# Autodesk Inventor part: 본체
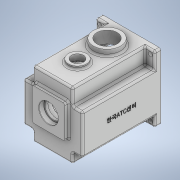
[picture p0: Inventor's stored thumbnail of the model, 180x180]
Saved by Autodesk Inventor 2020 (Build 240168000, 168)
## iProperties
Created: 2022-01
Part Number: 본체
Material: 일반
Document SubType Name: Modeling
Designer: user
Density: 1 g/cm^3
Appearance: 기본값
Mass: 520.049 g
Surface Area: 1170.68 cm^2
Volume: 520.049 cm^3
Author: user
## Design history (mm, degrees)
sketch "스케치1"
  geometry: L1 (-49, -55)-(49, -55); L2 (49, -55)-(49, 55); L3 (49, 55)-(-49, 55); L4 (-49, 55)-(-49, -55); L5 (-49, -55)-(49, 55); L6 (49, -55)-(-49, 55); 1 further point
  constraints: 12 end point, 2 midpoint, 2 parallel, 1 horizontal, 1 perpendicular
  dimensions: "d0" = 98 distance of L3.end L2.end; "d1" = 110 distance of L2.end L1.end
extrude "돌출1" new body sketch "스케치1" stored distance "d2" = 130; taper "d3" = 0 deg
sketch "스케치2"
  geometry: L1 (49, 55)-(-49, 55) reference; L2 (49, -55)-(49, 55) reference; L3 (33, 55)-(49, 55); L4 (49, 55)-(49, 28); L5 (49, 28)-(33, 28); L6 (33, 28)-(33, 55); L7 (33, -38)-(49, -38); L8 (49, -38)-(49, -55); L9 (49, -55)-(33, -55); L10 (33, -55)-(33, -38); L11 (-49, 55)-(-49, -55) reference; L12 (-49, 55)-(-33, 55); L13 (-33, 55)-(-33, 28); L14 (-33, 28)-(-49, 28); L15 (-49, 28)-(-49, 55); L16 (-49, -55)-(49, -55) reference; L17 (-49, -38)-(-33, -38); L18 (-33, -38)-(-33, -55); L19 (-33, -55)-(-49, -55); L20 (-49, -55)-(-49, -38); 5 further points
  constraints: 32 end point, 8 parallel, 8 point on line, 4 horizontal, 4 perpendicular
  dimensions: "d4" = 27 distance of L5.end L3.start; "d5" = 17 distance of L9.end L7.start; "d6" = 27 distance of L12.end L13.end; "d7" = 17 distance of L17.end L18.end; "d8" = 16 distance of L13.end L14.end; "d9" = 16 distance of L4.end L5.end
extrude "돌출2" cut sketch "스케치2" distance "d10" = 120; taper "d11" = 0 deg
sketch "스케치3"
  geometry: L1 (-27, -21)-(27, -21); L2 (27, -21)-(27, 33); L3 (27, 33)-(-27, 33); L4 (-27, 33)-(-27, -21); L5 (-27, -21)-(27, 33); L6 (27, -21)-(-27, 33); L7 (-33, -55)-(33, -55) reference; 3 further points
  constraints: 12 end point, 3 midpoint, 2 parallel, 1 horizontal, 1 perpendicular, 1 vertical alignment
  dimensions: "d12" = 54 distance of L3.end L2.end; "d13" = 54 distance of L2.end L1.end; "d14" = 61 distance from line of L7 point (0, 6)
extrude "돌출3" join sketch "스케치3" distance "d15" = 7; taper "d16" = 0 deg
sketch "스케치4"
  geometry: L1 (-33, -55)-(33, -55) reference; 2 further points
  constraints: 1 vertical alignment
  dimensions: "d17" = 61 distance from line of L1 point (0, 6)
hole "구멍1" sketch "스케치4" at (0, 6) diameter "d18" = 28; stored, may be unused: countersink angle "d22" = 90 deg, drill point angle "d24" = 118 deg; dims "d19" = 6, "d20" = 32, "d21" = 8.3, "d23" = 8
sketch "스케치5"
  geometry: L1 (-23, 12.067)-(23, 12.067); L2 (23, 12.067)-(23, 45); L3 (23, 45)-(-23, 45); L4 (-23, 45)-(-23, 12.067); L5 (-23, 12.067)-(23, 45); L6 (23, 12.067)-(-23, 45); L7 (-49, -55)-(49, -55) reference; C1 r 42 at (0, -5); 6 further points
  constraints: 12 end point, 4 midpoint, 2 parallel, 2 vertical alignment, 1 centre point, 1 horizontal, 1 perpendicular
  dimensions: "d25" = 46 distance of L2.end L3.end; "d26" = 84 diameter of C1; "d27" = 50 distance from line of L7 C1.centre; "d28" = 50 distance from line of C1.centre L3
extrude "돌출4" cut sketch "스케치5" distance "d29" = 121; taper "d30" = 0 deg
sketch "스케치6"
  geometry: L1 (23, 45)-(23, 30.143) reference; L2 (-23, 30.143)-(-23, 45) reference; L3 (-23, 45)-(23, 45) reference; L4 (-49, 55)-(-49, -55) reference; L5 (-49, -55)-(49, -55) reference; L6 (49, -55)-(49, 55) reference; L7 (49, 55)-(-49, 55) reference; L8 (26, 31.729)-(26, 48); L9 (26, 48)-(-26, 48); L10 (-26, 48)-(-26, 31.729); A1 r 42 centre (0, -5) between (-23, 30.143) and (23, 30.143) reference; A2 r 45 centre (0, -5) between (-26, 31.729) and (26, 31.729); 1 further point
  constraints: 6 end point, 2 point on circle, 1 centre point, 3 other
  dimensions: "d31" = 3 radial gap between concentric circles of A1 A2
extrude "돌출5" cut sketch "스케치6" distance "d32" = 9; taper "d33" = 0 deg
sketch "스케치7" dims "d34" = 72
  geometry: L1 (33, -55)-(49, -55) reference; L2 (36, -1)-(45.636, -1); L3 (36, -9)-(46.901, -9); L4 (49, 28)-(49, -38) reference; L5 (45.636, -1)-(46.901, -9); A1 r 4 centre (36, -5) between (36, -1) and (36, -9); 2 further points
  constraints: 6 end point, 2 horizontal alignment, 2 point on circle, 2 tangent, 1 centre point, 1 horizontal, 1 perpendicular, 1 vertical alignment, 2 other
  dimensions: "d35" = 50 distance from line of L1 point (0, -5); "d36" = 8 diameter of A1
extrude "돌출6" join sketch "스케치7" distance "d37" = 121; taper "d38" = 0 deg
sketch "스케치8"
  geometry: L1 (49, -121)-(-3, -121) reference; 2 further points
  constraints: 1 vertical alignment
  dimensions: "d39" = 40 distance from line of L1 point (23, -81)
sketch "스케치9"
  geometry: L1 (0, 0)-(98, 0) reference; C1 r 22.5 at (49, -40); 1 further point
  constraints: 1 centre point, 1 vertical alignment
  dimensions: "d40" = 45 diameter of C1; "d41" = 40 distance from line of L1 C1.centre
extrude "돌출7" join sketch "스케치9" distance "d42" = 10; taper "d43" = 0 deg
hole "구멍2" sketch "스케치8" diameter "d44" = 33.376; stored, may be unused: countersink angle "d48" = 90 deg, drill point angle "d50" = 118 deg; dims "d45" = 70, "d46" = 32, "d47" = 8.3, "d49" = 77.3
sketch "스케치10"
  geometry: L1 (49, -121)-(-3, -121) reference; 2 further points
  constraints: 1 vertical alignment
  dimensions: "d51" = 89 distance from line of L1 point (23, -32)
sketch "스케치11"
  geometry: L1 (0, 0)-(98, 0) reference; C1 r 15 at (49, -89); 1 further point
  constraints: 1 centre point
  dimensions: "d52" = 30 diameter of C1; "d53" = 89 distance from line of L1 C1.centre
extrude "돌출8" join sketch "스케치11" distance "d54" = 5; taper "d55" = 0 deg
hole "구멍3" sketch "스케치10" diameter "d56" = 20; stored, may be unused: countersink angle "d60" = 90 deg, drill point angle "d62" = 118 deg; dims "d57" = 70, "d58" = 30, "d59" = 5, "d61" = 77.3
chamfer "모따기1" distance "d63" = 1; stored, may be unused: second distance "d64" = 2, angle "d65" = 45 deg
sketch "스케치12"
  geometry: L1 (33, -55)-(-33, -55) reference; C1 r 21 at (0, 6); C2 r 15 at (0, -25); 3 further points
  constraints: 2 centre point, 2 vertical alignment
  dimensions: "d66" = 42 diameter of C1; "d67" = 30 diameter of C2; "d68" = 31 distance of C2.centre C1.centre; "d69" = 30 distance from line of L1 C2.centre
extrude "돌출9" join sketch "스케치12" distance "d70" = 7; taper "d71" = 0 deg
sketch "스케치13"
  geometry: L1 (-49, 55)-(-49, -55) reference; L2 (49, 55)-(-49, 55) reference; 2 further points
  dimensions: "d72" = 7 distance from line of L1 point (-42, 48); "d73" = 7 distance from line of L2 point (-42, 48)
hole "구멍4" sketch "스케치13" at (-42, 48) diameter "d74" = 7; stored, may be unused: countersink angle "d78" = 90 deg, drill point angle "d80" = 118 deg; dims "d75" = 70, "d76" = 30, "d77" = 5, "d79" = 77.3
fillet "모깎기1" dims "d87" = 6
fillet "모깎기2" dims "d88" = 3
fillet "모깎기3" dims "d89" = 3
fillet "모깎기4" dims "d90" = 6
sketch "스케치14"
  geometry: A1 r 21 centre (0, 6) between (8.978, -12.984) and (-8.978, -12.984) reference; 2 further points
  constraints: 1 coincident
hole "구멍5" sketch "스케치14" at (0, 6) diameter "d91" = 35; stored, may be unused: countersink angle "d95" = 90 deg, drill point angle "d97" = 0 deg; dims "d92" = 70, "d93" = 30, "d94" = 5, "d96" = 10
sketch "스케치15"
  geometry: A1 r 15 centre (0, -25) between (-8.978, -12.984) and (8.978, -12.984) reference; 2 further points
  constraints: 1 coincident
hole "구멍6" sketch "스케치15" at (0, -25) diameter "d98" = 22; stored, may be unused: countersink angle "d102" = 90 deg, drill point angle "d104" = 0 deg; dims "d99" = 70, "d100" = 30, "d101" = 5, "d103" = 7
sketch "스케치16"
  geometry: A1 r 15 centre (0, 0) between (-8.978, 12.016) and (8.978, 12.016) reference; 2 further points
  constraints: 1 coincident
hole "구멍7" sketch "스케치16" at (0, 0) diameter "d105" = 19; stored, may be unused: countersink angle "d109" = 90 deg, drill point angle "d111" = 0 deg; dims "d106" = 70, "d107" = 30, "d108" = 5, "d110" = 3
fillet "모깎기5" dims "d112" = 3
fillet "모깎기6" dims "d113" = 0.3
chamfer "모따기2" distance "d114" = 1; stored, may be unused: second distance "d115" = 2, angle "d116" = 45 deg
chamfer "모따기3" distance "d117" = 1; stored, may be unused: second distance "d118" = 2, angle "d119" = 45 deg
fillet "모깎기7" dims "d120" = 0.3
chamfer "모따기4" distance "d121" = 0.8; stored, may be unused: second distance "d122" = 2, angle "d123" = 30 deg
sketch "스케치17"
  geometry: A1 r 4 centre (36, -5) between (36, -1) and (36, -9) reference; 2 further points
  constraints: 1 coincident
hole "구멍8" sketch "스케치17" at (36, -5) diameter "d124" = 3.242; stored, may be unused: countersink angle "d128" = 90 deg, drill point angle "d130" = 118 deg; dims "d125" = 7, "d126" = 30, "d127" = 5, "d129" = 9
fillet "모깎기8" dims "d131" = 3
fillet "모깎기9" dims "d132" = 3
fillet "모깎기10" dims "d133" = 3
fillet "모깎기11" dims "d134" = 3
fillet "모깎기12" dims "d135" = 3
fillet "모깎기13" dims "d136" = 3
fillet "모깎기14" dims "d137" = 3
fillet "모깎기15" dims "d138" = 3
fillet "모깎기16" dims "d139" = 3
fillet "모깎기17" dims "d140" = 3
fillet "모깎기18" dims "d141" = 3
fillet "모깎기19" dims "d142" = 3
chamfer "모따기5" distance "d143" = 1; stored, may be unused: second distance "d144" = 2, angle "d145" = 30 deg
fillet "모깎기20" dims "d146" = 3
sketch "스케치18"
  geometry: L1 (120, 90)-(0, 90) reference; L2 (-3, 87)-(-3, 66) reference; 2 further points
  constraints: 1 other
  dimensions: "d147" = 60 distance from line of L1 point (62, 30); "d148" = 65 distance from line of L2 point (62, 30)
feature "엠보싱1" sketch "스케치18" dims "d4" = 27, "d5" = 17, "d6" = 27, "d7" = 17, "d8" = 16, "d9" = 16, "d149" = 0.5, "d150" = 0
node "솔리드1"
mirror "미러1"
pattern_linear "직사각형 패턴1" dims "d83" = 84, "d86" = 96
mirror "미러2"
node "투영된 루프1"
feature "A9D066F2-1C7D-4E18-AEED-F7BC21143FA4" dims "d18" = 28, "d19" = 6, "d20" = 32, "d21" = 8.3, "d22" = 90 deg, "d23" = 8, "d24" = 118 deg
